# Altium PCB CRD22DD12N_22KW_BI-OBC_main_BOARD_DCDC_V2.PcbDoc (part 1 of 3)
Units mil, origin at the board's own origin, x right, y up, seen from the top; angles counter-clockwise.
Board outline 9308.07 x 7086.6 mil, 4 copper layers (TOP, GND02, POWER03, BOTTOM), stack 74.3 mil thick; 339 components, 177 nets, 874 pads, 199 vias.
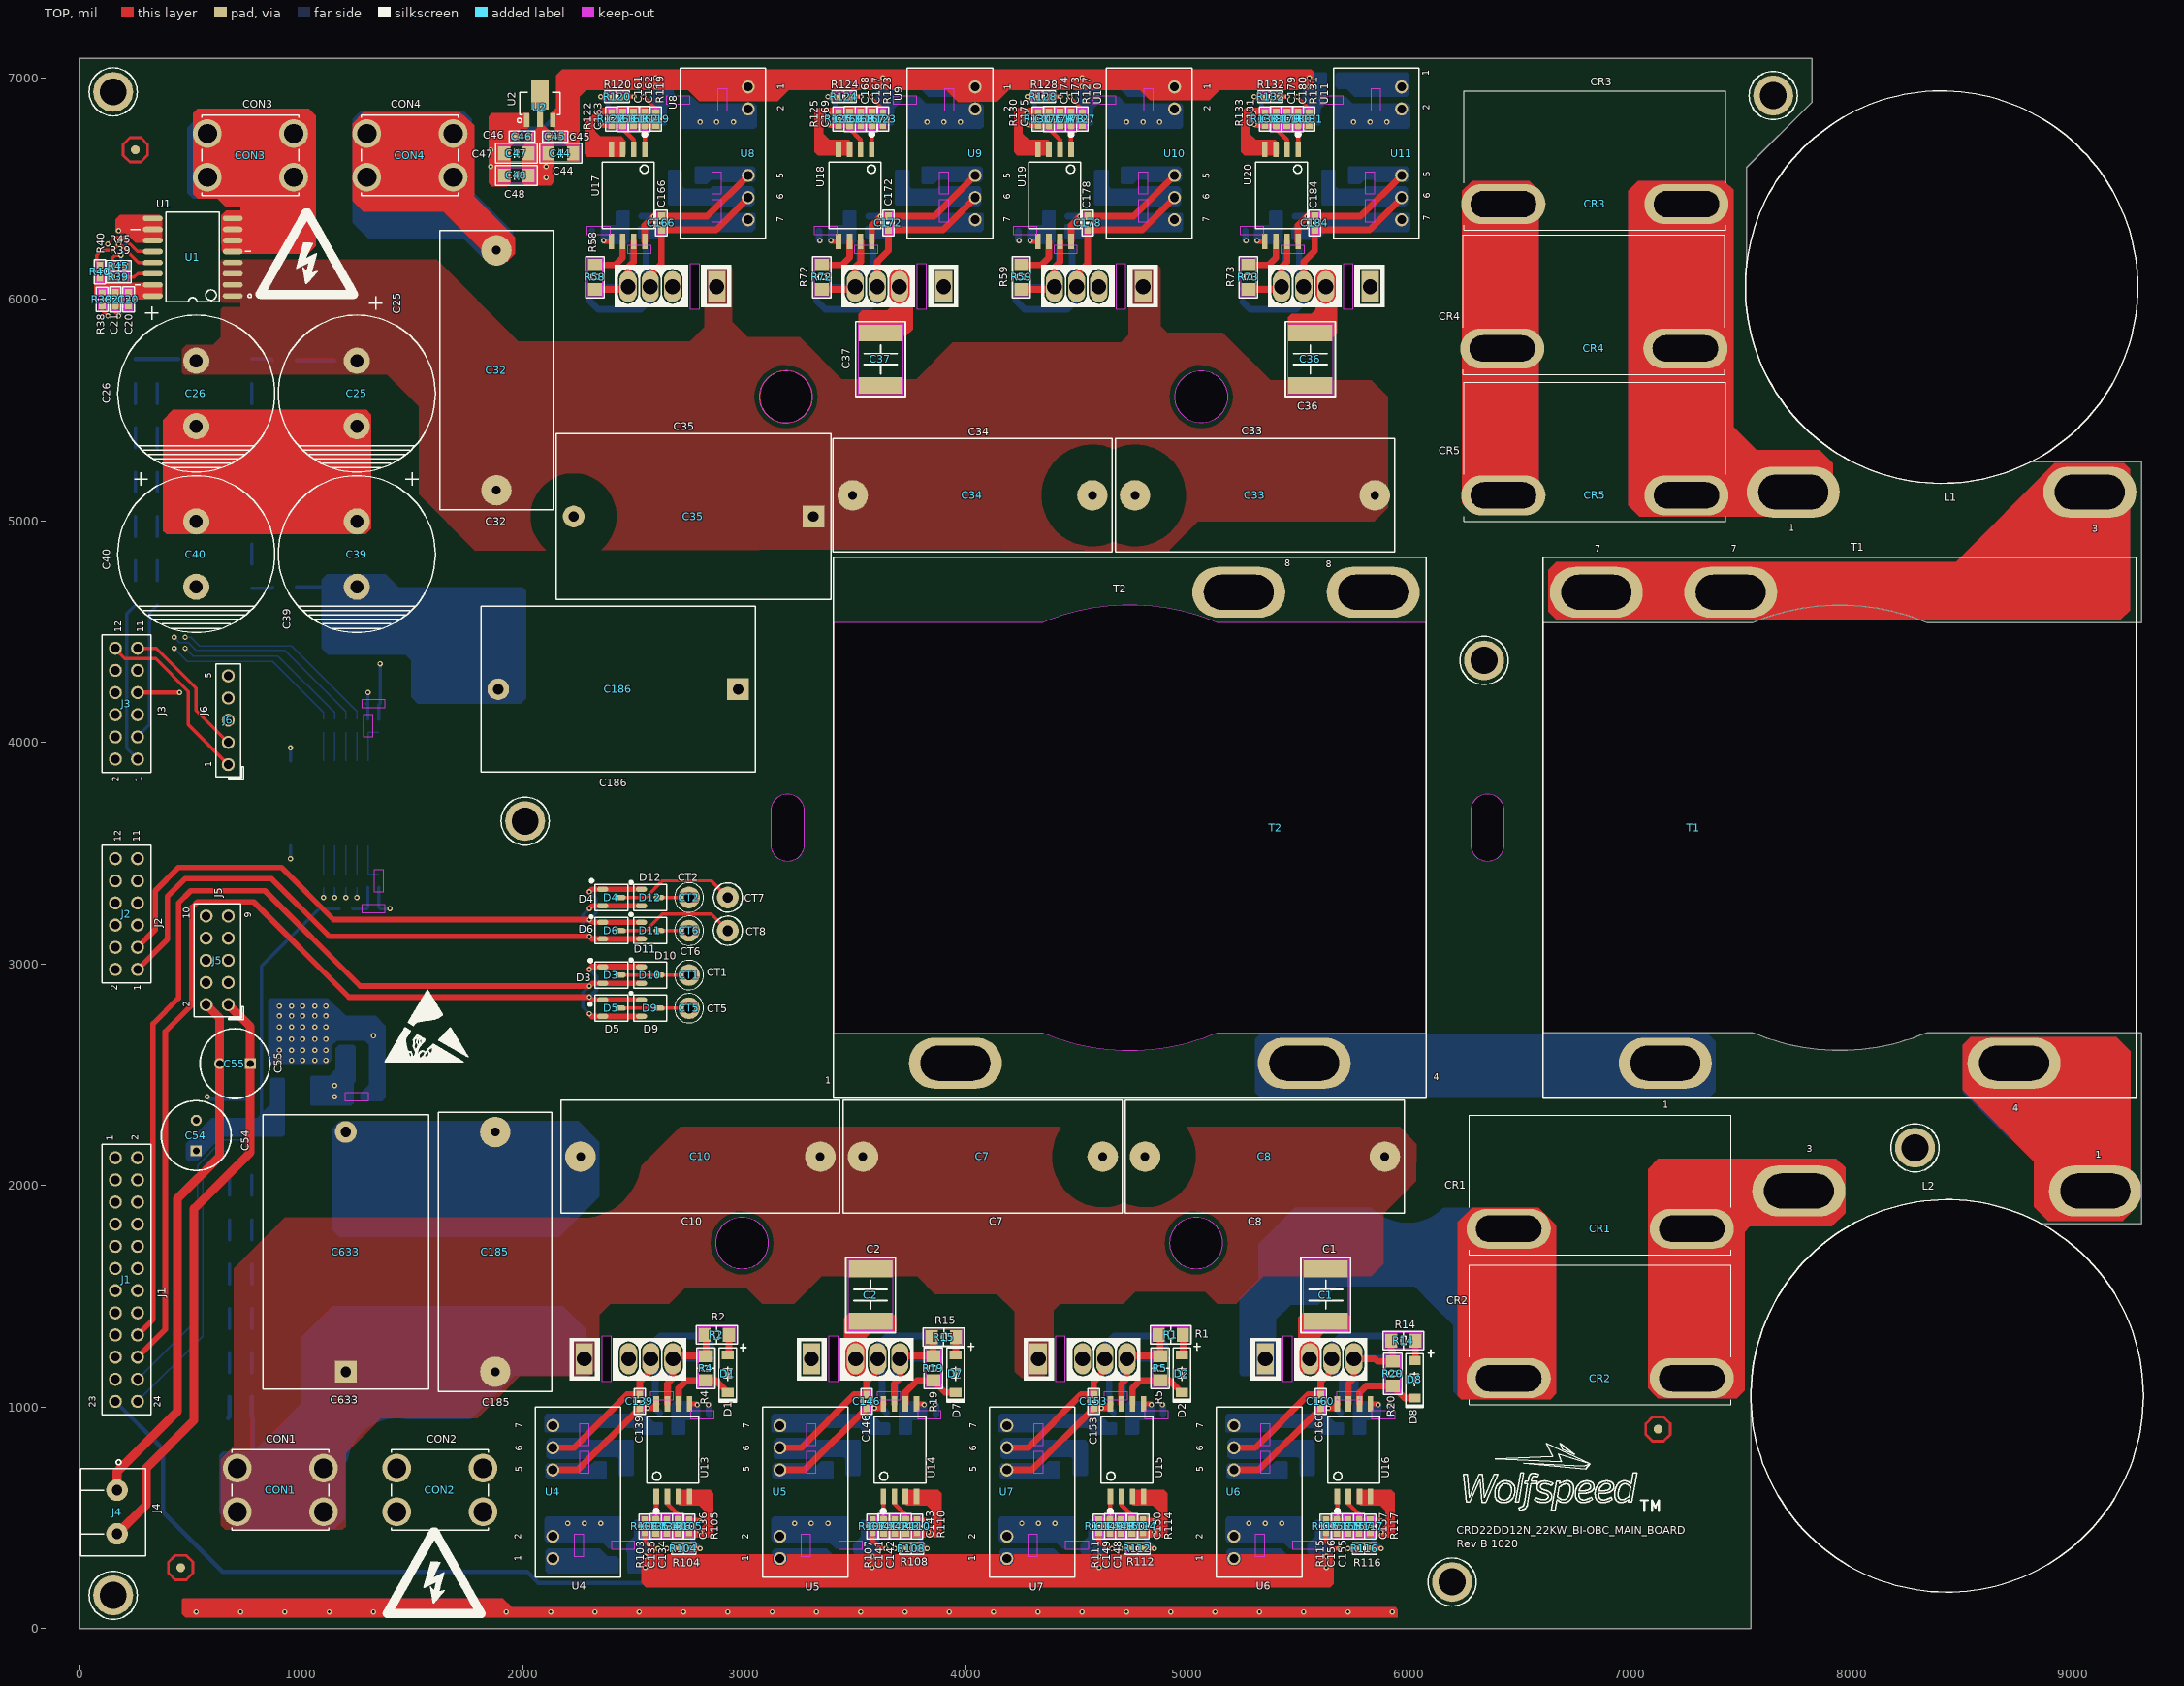
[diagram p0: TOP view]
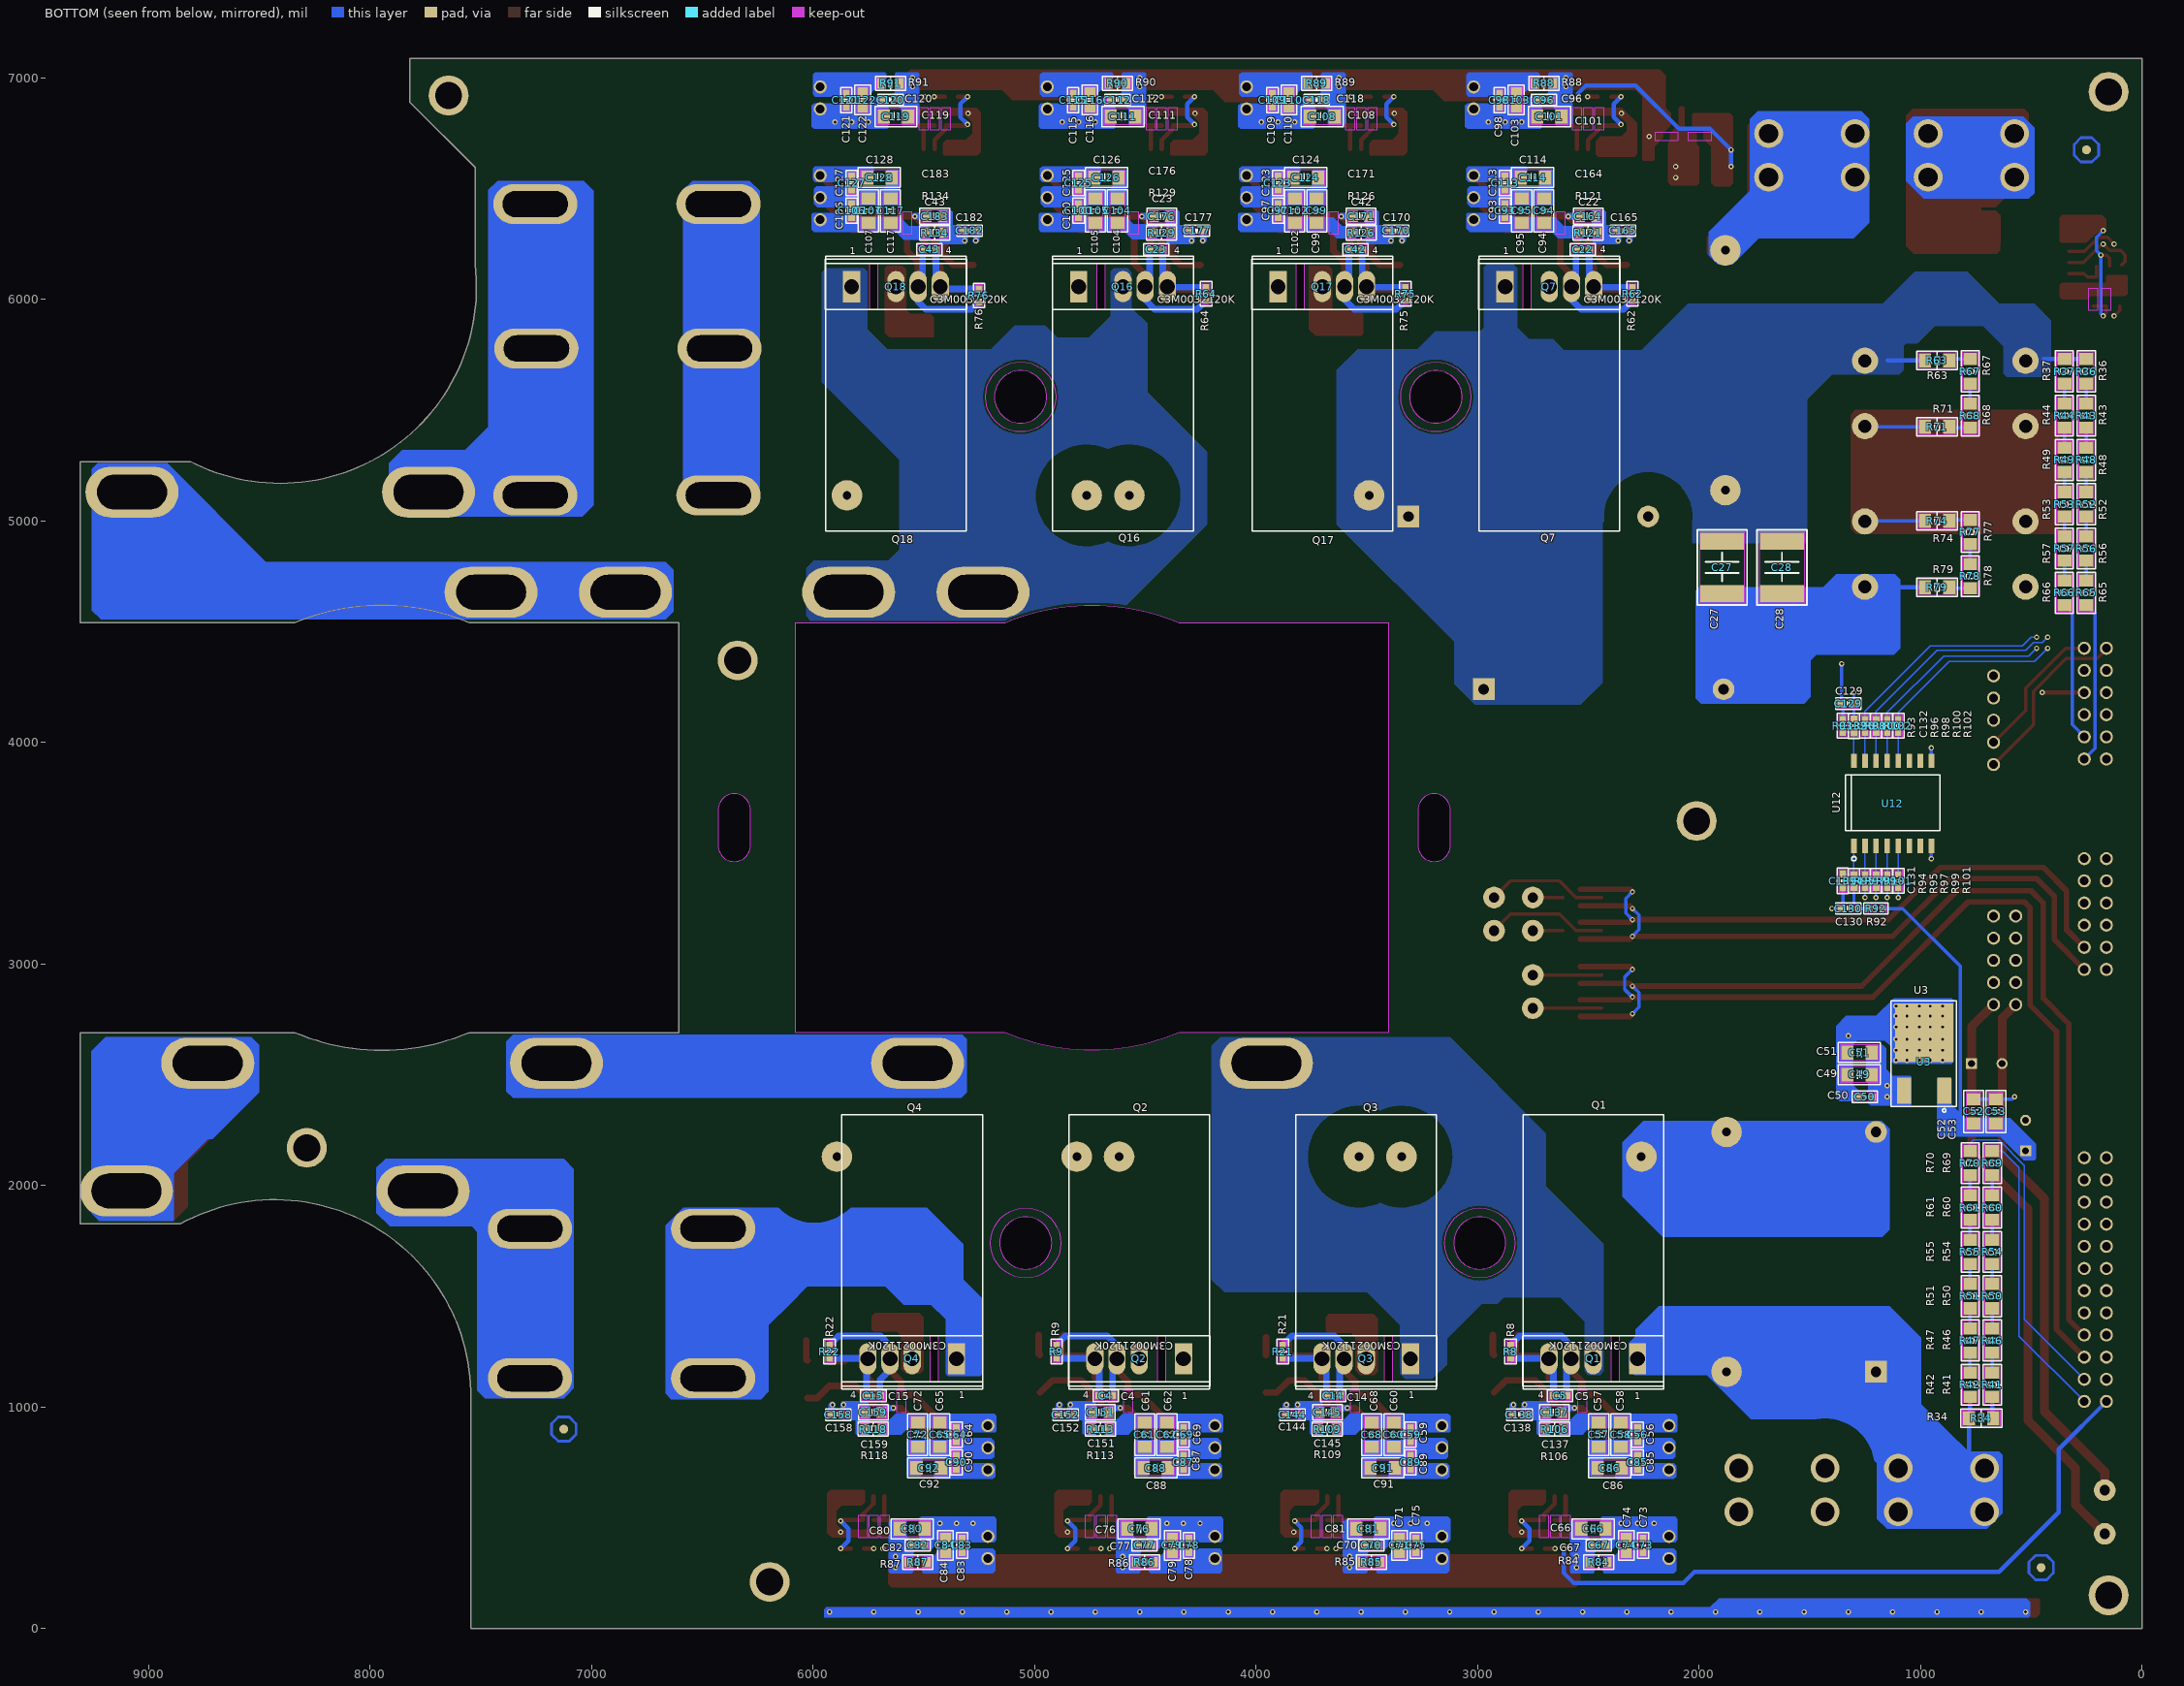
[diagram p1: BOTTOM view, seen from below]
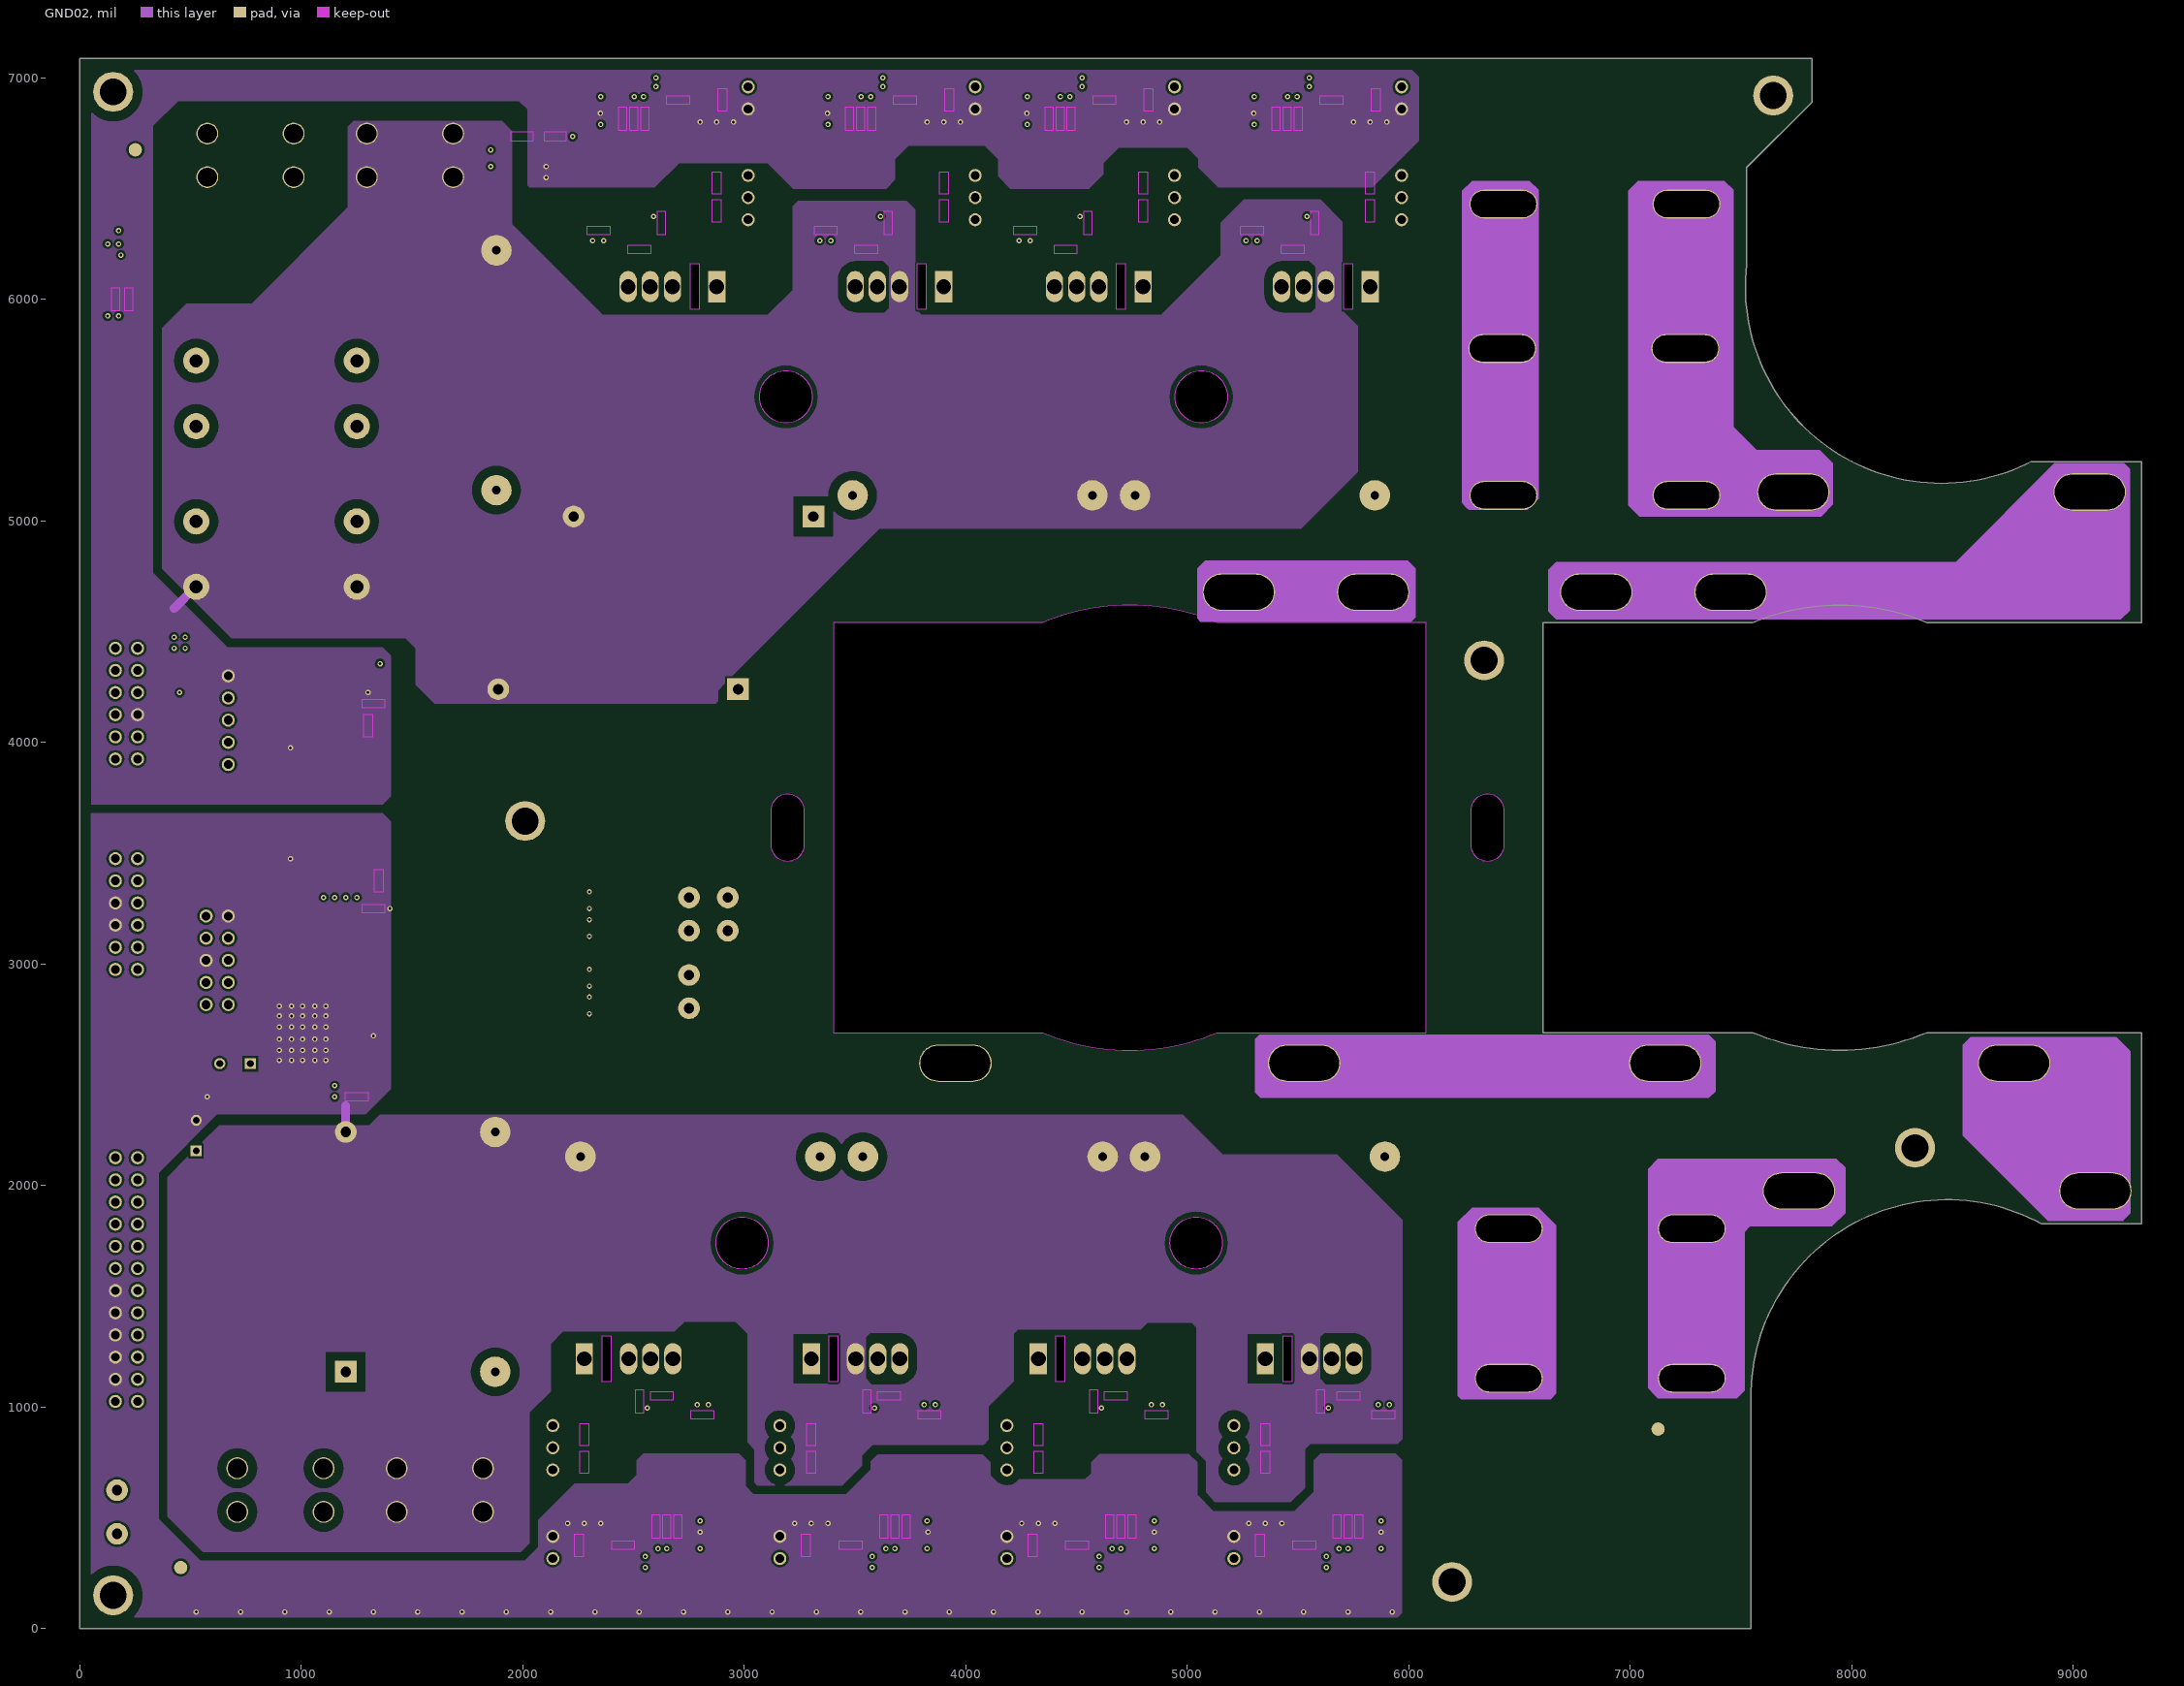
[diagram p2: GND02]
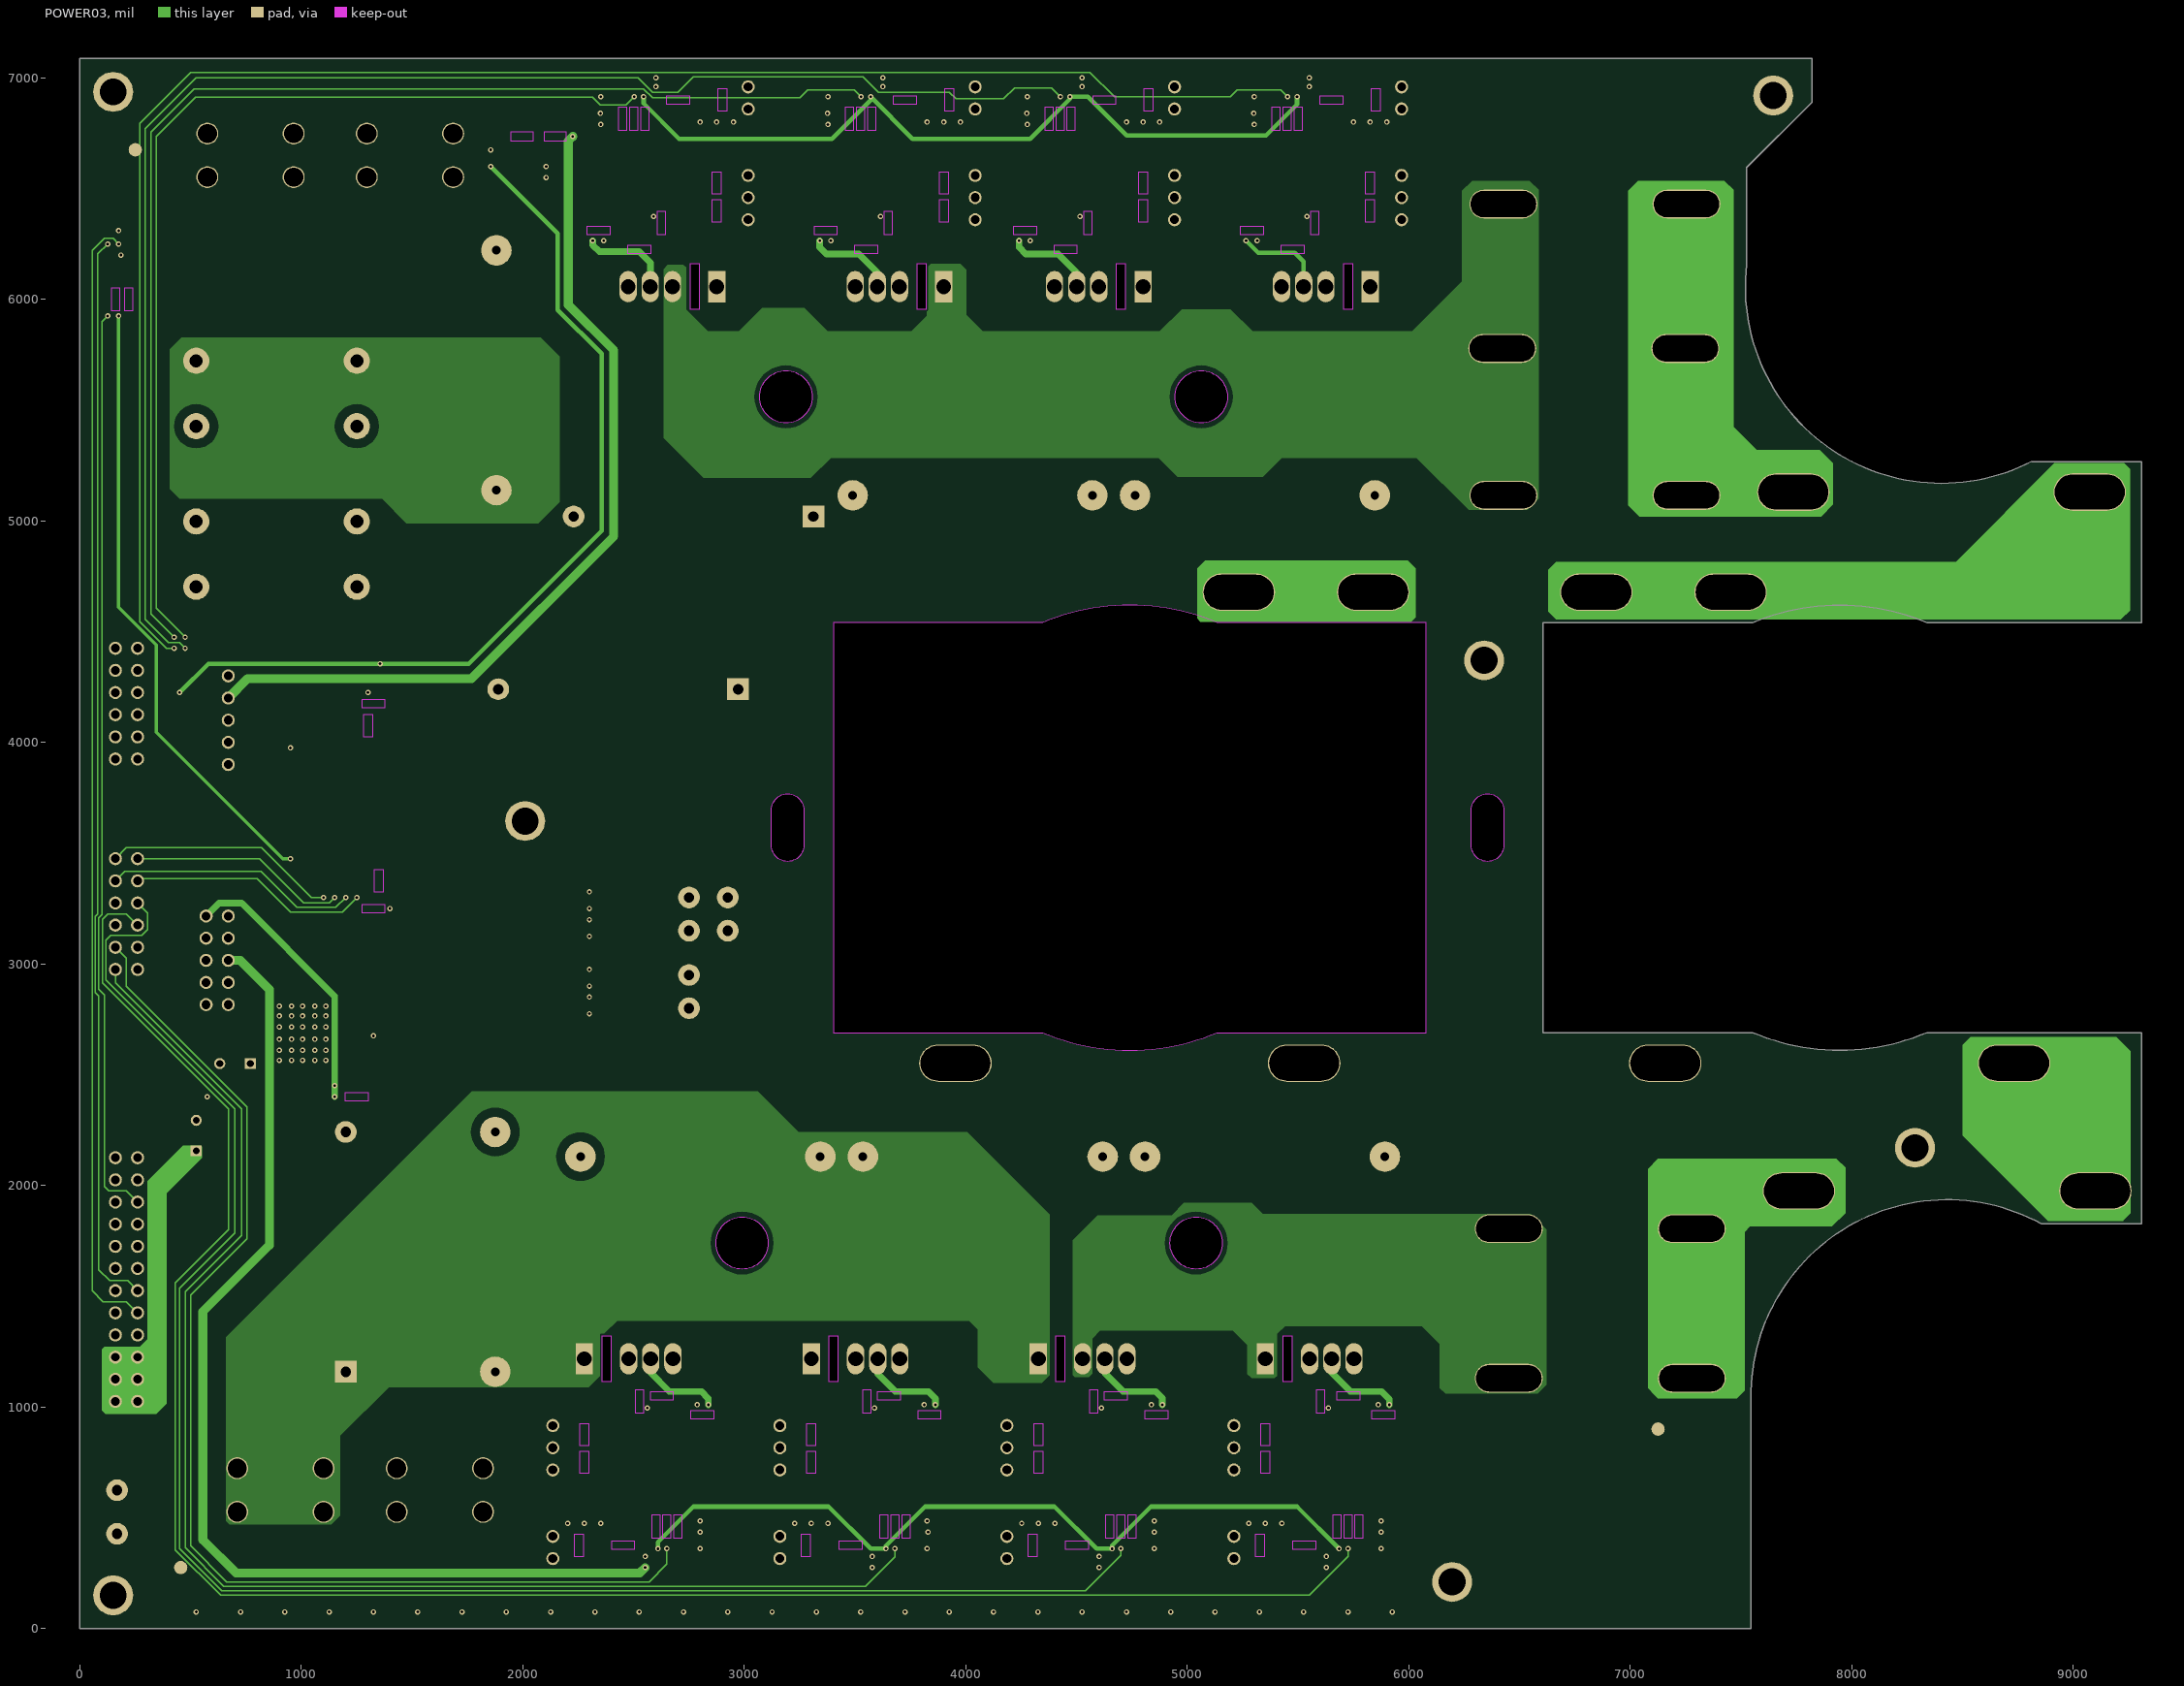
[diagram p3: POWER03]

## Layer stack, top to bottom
Top Solder: solder mask 0.4, Solder Resist, Dk 3.5
TOP: signal copper 2.4
Dielectric 1: core 4.4, FR-4, Dk 4.5
GND02: signal copper 1.2
Dielectric2: core 58.3, FR-4, Dk 1
POWER03: signal copper 1.2
Dielectric3: core 4.4, FR-4, Dk 1
BOTTOM: signal copper 2.4
Bottom Solder: solder mask 0.4, Solder Resist, Dk 3.5

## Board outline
6606,2690 6606,4540 7552.56,4540 cw(c7945.5,3615.03) 9308.07,4540 9308.07,5267.93 8811.07,5267.93 cw(c8405,6055.2) 7525,6595 7820,6890 7820,7086.6 0,7086.6 0,0 7544.23,0 7544.23,229.23 7544.23,1039.59 cw(c8430,1049.8) 9308.07,1826.55 9308.07,2690 8338.44,2690 cw(c7945.5,3615)
cut-out: 6355,3767.5 cw(c6355,3693.5) 6429,3693.5 6429,3536.5 cw(c6355,3536.5) 6355,3462.5 cw(c6355,3536.5) 6281,3536.5 6281,3693.5 cw(c6355,3693.5)
cut-out: 3195,3767.5 cw(c3195,3693.5) 3269,3693.5 3269,3536.5 cw(c3195,3536.5) 3195,3462.5 cw(c3195,3536.5) 3121,3536.5 3121,3693.5 cw(c3195,3693.5)
cut-out: 2989.5,1622 cw(c2989.5,1740) 2871.5,1740 cw(c2989.5,1740) 2989.5,1858 cw(c2989.5,1740) 3107.5,1740 cw(c2989.5,1740)
cut-out: 5039.5,1622 cw(c5039.5,1740) 4921.5,1740 cw(c5039.5,1740) 5039.5,1858 cw(c5039.5,1740) 5157.5,1740 cw(c5039.5,1740)
cut-out: 5062.5,5442 cw(c5062.5,5560) 4944.5,5560 cw(c5062.5,5560) 5062.5,5678 cw(c5062.5,5560) 5180.5,5560 cw(c5062.5,5560)
cut-out: 3187.5,5442 cw(c3187.5,5560) 3069.5,5560 cw(c3187.5,5560) 3187.5,5678 cw(c3187.5,5560) 3305.5,5560 cw(c3187.5,5560)
cut-out: 5133.44,4540 ccw(c4740.5,3615.02) 3402,4540 3402,2690 4347.56,2690 ccw(c4740.5,3615) 6079,2690 6079,4540
cut-out: 5432.31,1322.05 5471.69,1322.05 5471.69,1113.38 5432.31,1113.38
cut-out: 4407.31,1322.05 4446.69,1322.05 4446.69,1113.38 4407.31,1113.38
cut-out: 3382.32,1322.05 3421.68,1322.05 3421.68,1113.38 3382.32,1113.38
cut-out: 2357.32,1322.05 2396.68,1322.05 2396.68,1113.38 2357.32,1113.38
cut-out: 5705.31,6161.61 5744.69,6161.61 5744.69,5952.95 5705.31,5952.95
cut-out: 4680.31,6161.61 4719.69,6161.61 4719.69,5952.95 4680.31,5952.95
cut-out: 3780.32,6161.61 3819.68,6161.61 3819.68,5952.95 3780.32,5952.95
cut-out: 2755.32,6161.61 2794.68,6161.61 2794.68,5952.95 2755.32,5952.95

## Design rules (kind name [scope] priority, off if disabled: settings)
Clearance [All] p1: gap=10 ignorepadtopadclearanceinfootprint=FALSE except(0: Arc-Hole Track-Hole SMDPad-Hole THPad-Hole Via-Hole Fill-Hole Poly-Hole Region-Hole Text-Hole)
PlaneConnect [All] p1: planeconnectstyle=Direct reliefexpansion=20 reliefentries=4 reliefconductorwidth=10 reliefairgap=10
PolygonConnect [All] p1: connectstyle=Direct reliefconductorwidth=10 reliefentries=4 polygonreliefangle="90 Angle" airgapwidth=10
RoutingVias [All] p1: holewidth=28 width=50 viastyle="Through Hole" minholewidth=28 minwidth=50 maxholewidth=28 maxwidth=50
SolderMaskExpansion [All] p1: expansion=4 istentingtop=FALSE
Width [All] p1: maxlimit=10 minlimit=10 preferedwidth=10 impedanceprofiledriven=TRUE minimp=60.000000 maximp=60.000000 favimp=60.000000
29 further rules are at their usual default settings.

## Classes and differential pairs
net class GAO: DCINPUT LEGA LEGB N17988090 N17988199 N17988317 N18067595 SLEGB VO+
net class DI: AGND N16148550 PGND SGND SPGND

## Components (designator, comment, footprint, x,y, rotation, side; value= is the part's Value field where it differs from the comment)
C1 "CAP NP_C2220_0U1" C2220 5625,1505 r270 top
C2 "CAP NP_C2220_0U1" C2220 3570,1505 r270 top
C4 "CAP NP_C0603_1N" C0603#1 4677,1050 r0 bottom
C5 "CAP NP_C0603_1N" C0603#1 2627,1050 r0 bottom
C7 "CAP NP_CAPFILM_31_5X12_5MM_2.2U" CAPFILM_31_5X12_5MM 4076.17,2130 r0 top
C8 "CAP NP_CAPFILM_31_5X12_5MM_2.2U" CAPFILM_31_5X12_5MM 5350,2130 r180 top
C10 "CAP NP_CAPFILM_31_5X12_5MM_2.2U" CAPFILM_31_5X12_5MM 2801.17,2130 r180 top
C14 "CAP NP_C0603_1N" C0603#1 3652,1050 r0 bottom
C15 "CAP NP_C0603_1N" C0603#1 5727,1050 r0 bottom
C20 "CAP NP_C0603_0.1U" C0603#2 220,6000 r270 top
C21 "CAP NP_C0603_1U" C0603#2 160,6000 r270 top
C22 "CAP NP_C0603_1N" C0603#2 2525,6225 r0 bottom
C23 "CAP NP_C0603_1N" C0603#2 4450,6225 r0 bottom
C25 "CAP POL_ECAP_D18P7_5_450V 180UF" ECAP_D18P7_5 1250,5575 r180 top
C26 "CAP POL_ECAP_D18P7_5_450V 180UF" ECAP_D18P7_5 525,5575 r180 top
C27 "CAP NP_C2220_0U1" C2220 1895,4790 r270 bottom
C28 "CAP NP_C2220_0U1" C2220 1625,4790 r270 bottom
C32 "CAP NP_CAPFILM_31_5X12_5MM_2.2U" CAPFILM_31_5X12_5MM 1880,5680 r90 top
C33 "CAP NP_CAPFILM_31_5X12_5MM_2.2U" CAPFILM_31_5X12_5MM 5305,5115 r180 top
C34 "CAP NP_CAPFILM_31_5X12_5MM_2.2U" CAPFILM_31_5X12_5MM 4030,5115 r0 top
C35 "CAP NP_CAPFILM_31_5X18_5MM_5U" CAPFILM_31_5X18_5MM 2770,5020 r180 top
C36 "CAP NP_C2220_0U1" C2220 5555,5730 r90 top
C37 "CAP NP_C2220_0U1" C2220 3615,5730 r90 top
C39 "CAP POL_ECAP_D18P7_5_450V 180UF" ECAP_D18P7_5 1250,4850 r180 top
C40 "CAP POL_ECAP_D18P7_5_450V 180UF" ECAP_D18P7_5 525,4850 r180 top
C42 "CAP NP_C0603_1N" C0603#2 3550,6225 r0 bottom
C43 "CAP NP_C0603_1N" C0603#2 5475,6225 r0 bottom
C44 "CAP NP_C1206_10U" C1206#1 2170.75,6659.25 r0 top
C45 "CAP NP_C0603_1U" C0603#2 2145.75,6734.25 r0 top
C46 "CAP NP_C0603_1U" C0603#2 1995.75,6734.25 r180 top
C47 "CAP NP_C1206_22U" C1206#1 1970.75,6659.25 r180 top
C48 "CAP NP_C1206_22U" C1206#1 1970.75,6559.25 r180 top
C49 "CAP NP_C1206_10U" C1206#2 1275,2500 r0 bottom
C50 "CAP NP_C0603_1U" C0603#1 1250,2400 r0 bottom
C51 "CAP NP_C1206_10U" C1206#2 1275,2600 r0 bottom
C52 "CAP NP_C1206_10U" C1206#1 759.25,2334.25 r270 bottom
C53 "CAP NP_C1206_10U" C1206#1 659.25,2334.25 r270 bottom
C54 "CAP POL_ECAP_D8P3_5_25V 220UF" ECAP_D8P3_5 525,2225 r90 top
C55 "CAP POL_ECAP_D8P3_5_25V 220UF" ECAP_D8P3_5 700,2550 r180 top
C56 "CAP NP_C0603_1UF" C0603#2 2277,875 r270 bottom
C57 "CAP NP_C1206_4U7" C1206#1 2452,875 r270 bottom
C58 "CAP NP_C1206_10UF" C1206#1 2352,875 r270 bottom
C59 "CAP NP_C0603_1UF" C0603#2 3302,875 r270 bottom
C60 "CAP NP_C1206_10UF" C1206#1 3377,875 r270 bottom
C61 "CAP NP_C1206_4U7" C1206#1 4502,875 r270 bottom
C62 "CAP NP_C1206_10UF" C1206#1 4402,875 r270 bottom
C64 "CAP NP_C0603_1UF" C0603#2 5352,875 r270 bottom
C65 "CAP NP_C1206_10UF" C1206#1 5427,875 r270 bottom
C66 "CAP NP_C1206_10UF" C1206#2 2477,450 r0 bottom
C67 "CAP NP_C0603_1UF" C0603#1 2452,375 r0 bottom
C68 "CAP NP_C1206_4U7" C1206#1 3477,875 r270 bottom
C69 "CAP NP_C0603_1UF" C0603#2 4327,875 r270 bottom
C70 "CAP NP_C0603_1UF" C0603#1 3479.17,375 r0 bottom
C71 "CAP NP_C0805_2U2" C0805#1 3352,375 r90 bottom
C72 "CAP NP_C1206_4U7" C1206#1 5527,875 r270 bottom
C73 "CAP NP_C0603_0U1" C0603#2 2252,375 r90 bottom
C74 "CAP NP_C0805_2U2" C0805#1 2327,375 r90 bottom
C75 "CAP NP_C0603_0U1" C0603#2 3277,375 r90 bottom
C76 "CAP NP_C1206_10UF" C1206#2 4527,450 r0 bottom
C77 "CAP NP_C0603_1UF" C0603#1 4502,375 r0 bottom
C78 "CAP NP_C0603_0U1" C0603#2 4302,375 r90 bottom
C79 "CAP NP_C0805_2U2" C0805#1 4377,375 r90 bottom
C80 "CAP NP_C1206_10UF" C1206#2 5552,450 r0 bottom
C81 "CAP NP_C1206_10UF" C1206#2 3491.67,450 r0 bottom
C82 "CAP NP_C0603_1UF" C0603#1 5527,375 r0 bottom
C83 "CAP NP_C0603_0U1" C0603#2 5327,375 r90 bottom
C84 "CAP NP_C0805_2U2" C0805#1 5402,375 r90 bottom
C85 "CAP NP_C0603_1UF" C0603#2 2277,750 r270 bottom
C86 "CAP NP_C1206_10UF" C1206#2 2402,725 r0 bottom
C87 "CAP NP_C0603_1UF" C0603#2 4327,750 r270 bottom
C88 "CAP NP_C1206_10UF" C1206#2 4452,725 r0 bottom
C89 "CAP NP_C0603_1UF" C0603#2 3302,750 r270 bottom
C90 "CAP NP_C0603_1UF" C0603#2 5352,750 r270 bottom
C91 "CAP NP_C1206_10UF" C1206#2 3427,725 r0 bottom
C92 "CAP NP_C1206_10UF" C1206#2 5477,725 r0 bottom
C93 "CAP NP_C0603_1UF" C0603#2 2875,6400 r90 bottom
C94 "CAP NP_C1206_4U7" C1206#1 2700,6400 r90 bottom
C95 "CAP NP_C1206_10UF" C1206#1 2800,6400 r90 bottom
C96 "CAP NP_C0603_1UF" C0603#2 2700,6900 r0 bottom
C97 "CAP NP_C0603_1UF" C0603#2 3900,6400 r90 bottom
C98 "CAP NP_C0603_0U1" C0603#2 2900,6900 r270 bottom
C99 "CAP NP_C1206_4U7" C1206#1 3725,6400 r90 bottom
C100 "CAP NP_C0603_1UF" C0603#2 4800,6400 r90 bottom
C101 "CAP NP_C1206_10UF" C1206#1 2675,6825 r0 bottom
C102 "CAP NP_C1206_10UF" C1206#1 3825,6400 r90 bottom
C103 "CAP NP_C0805_2U2" C0805#1 2825,6900 r270 bottom
C104 "CAP NP_C1206_4U7" C1206#1 4625,6400 r90 bottom
C105 "CAP NP_C1206_10UF" C1206#1 4725,6400 r90 bottom
C106 "CAP NP_C0603_1UF" C0603#2 5825,6400 r90 bottom
C107 "CAP NP_C1206_10UF" C1206#1 5750,6400 r90 bottom
C108 "CAP NP_C1206_10UF" C1206#1 3700,6825 r0 bottom
C109 "CAP NP_C0603_0U1" C0603#2 3925,6900 r270 bottom
C110 "CAP NP_C0805_2U2" C0805#1 3850,6900 r270 bottom
C111 "CAP NP_C1206_10UF" C1206#1 4600,6825 r0 bottom
C112 "CAP NP_C0603_1UF" C0603#2 4625,6900 r0 bottom
C113 "CAP NP_C0603_1UF" C0603#2 2875,6525 r90 bottom
C114 "CAP NP_C1206_10UF" C1206#1 2750,6550 r0 bottom
C115 "CAP NP_C0603_0U1" C0603#2 4825,6900 r270 bottom
C116 "CAP NP_C0805_2U2" C0805#1 4750,6900 r270 bottom
C117 "CAP NP_C1206_4U7" C1206#1 5650,6400 r90 bottom
C118 "CAP NP_C0603_1UF" C0603#2 3725,6900 r0 bottom
C119 "CAP NP_C1206_10UF" C1206#1 5625,6825 r0 bottom
C120 "CAP NP_C0603_1UF" C0603#2 5650,6900 r0 bottom
C121 "CAP NP_C0603_0U1" C0603#2 5850,6900 r270 bottom
C122 "CAP NP_C0805_2U2" C0805#1 5775,6900 r270 bottom
C123 "CAP NP_C0603_1UF" C0603#2 3900,6525 r90 bottom
C124 "CAP NP_C1206_10UF" C1206#1 3775,6550 r0 bottom
C125 "CAP NP_C0603_1UF" C0603#2 4800,6525 r90 bottom
C126 "CAP NP_C1206_10UF" C1206#1 4675,6550 r0 bottom
C127 "CAP NP_C0603_1UF" C0603#2 5825,6525 r90 bottom
C128 "CAP NP_C1206_10UF" C1206#1 5700,6550 r0 bottom
C129 "CAP NP_C0603_0U1" C0603#1 1325,4175 r0 bottom
C130 "CAP NP_C0603_0U1" C0603#2 1325,3250 r0 bottom
C131 "CAP NP_C0603_0U1" C0603#2 1350,3375 r90 bottom
C132 "CAP NP_C0603_0U1" C0603#2 1300,4075 r270 bottom
C134 "CAP NP_C0603_1U" C0603#2 2650,460.68 r270 top
C135 "CAP NP_C0603_0.1U" C0603#2 2600,460.68 r270 top
C136 "CAP NP_C0603_1N" C0603#2 2700,460.68 r270 top
C137 "CAP NP_C0805_2.2U" C0805#2 2652,975 r0 bottom
C138 "CAP NP_C0603_1U" C0603#2 2810,965 r0 bottom
C139 "CAP NP_C0603_1U" C0603#2 2527,1025 r270 top
C141 "CAP NP_C0603_1U" C0603#2 3629.17,460.68 r270 top
C142 "CAP NP_C0603_0.1U" C0603#2 3679.17,460.68 r270 top
C143 "CAP NP_C0603_1N" C0603#2 3729.17,460.68 r270 top
C144 "CAP NP_C0603_1U" C0603#2 3835,965 r0 bottom
C145 "CAP NP_C0805_2.2U" C0805#2 3677,975 r0 bottom
C146 "CAP NP_C0603_1U" C0603#2 3552,1025 r270 top
C148 "CAP NP_C0603_1U" C0603#2 4700,460.68 r270 top
C149 "CAP NP_C0603_0.1U" C0603#2 4650,460.68 r270 top
C150 "CAP NP_C0603_1N" C0603#2 4750,460.68 r270 top
C151 "CAP NP_C0805_2.2U" C0805#2 4702,975 r0 bottom
C152 "CAP NP_C0603_1U" C0603#2 4860,965 r0 bottom
C153 "CAP NP_C0603_1U" C0603#2 4577,1025 r270 top
C155 "CAP NP_C0603_1U" C0603#2 5725,460.68 r270 top
C156 "CAP NP_C0603_0.1U" C0603#2 5675,460.68 r270 top
C157 "CAP NP_C0603_1N" C0603#2 5775,460.68 r270 top
C158 "CAP NP_C0603_1U" C0603#2 5885,965 r0 bottom
C159 "CAP NP_C0805_2.2U" C0805#2 5727,975 r0 bottom
C160 "CAP NP_C0603_1U" C0603#2 5602,1025 r270 top
C161 "CAP NP_C0603_1U" C0603#2 2500,6814.32 r90 top
C162 "CAP NP_C0603_0.1U" C0603#2 2550,6814.32 r90 top
C163 "CAP NP_C0603_1N" C0603#2 2450,6814.32 r90 top
C164 "CAP NP_C0805_2.2U" C0805#1 2500,6375 r0 bottom
C165 "CAP NP_C0603_1U" C0603#1 2342,6310 r0 bottom
C166 "CAP NP_C0603_1U" C0603#2 2625,6344.66 r90 top
C167 "CAP NP_C0603_1U" C0603#2 3575,6814.32 r90 top
C168 "CAP NP_C0603_0.1U" C0603#2 3525,6814.32 r90 top
C169 "CAP NP_C0603_1N" C0603#2 3475,6814.32 r90 top
C170 "CAP NP_C0603_1U" C0603#1 3367,6310 r0 bottom
C171 "CAP NP_C0805_2.2U" C0805#1 3525,6375 r0 bottom
C172 "CAP NP_C0603_1U" C0603#2 3650,6344.66 r90 top
C173 "CAP NP_C0603_0.1U" C0603#2 4475,6814.32 r90 top
C174 "CAP NP_C0603_1U" C0603#2 4425,6814.32 r90 top
C175 "CAP NP_C0603_1N" C0603#2 4375,6814.32 r90 top
C176 "CAP NP_C0805_2.2U" C0805#1 4425,6375 r0 bottom
C177 "CAP NP_C0603_1U" C0603#1 4267,6310 r0 bottom
C178 "CAP NP_C0603_1U" C0603#2 4550,6344.66 r90 top
C179 "CAP NP_C0603_1U" C0603#2 5450,6814.32 r90 top
C180 "CAP NP_C0603_0.1U" C0603#2 5500,6814.32 r90 top
C181 "CAP NP_C0603_1N" C0603#2 5400,6814.32 r90 top
C182 "CAP NP_C0603_1U" C0603#1 5292,6310 r0 bottom
C183 "CAP NP_C0805_2.2U" C0805#1 5450,6375 r0 bottom
C184 "CAP NP_C0603_1U" C0603#2 5575,6344.66 r90 top
C185 "CAP NP_CAPFILM_31_5X12_5MM_2.2U" CAPFILM_31_5X12_5MM 1875,1700 r90 top
C186 "CAP NP_CAPFILM_31_5X18_5MM_5U" CAPFILM_31_5X18_5MM 2430,4240 r180 top
C633 "CAP NP_CAPFILM_31_5X18_5MM_5U" CAPFILM_31_5X18_5MM 1200,1700 r90 top
CON1 "CONNECTER_THREAD4_9P9X5_1110X92" THREAD4_9P9X5_1110X920 905,625 r180 top
CON2 "CONNECTER_THREAD4_9P9X5_1110X92" THREAD4_9P9X5_1110X920 1625,625 r180 top
CON3 "CONNECTER_THREAD4_9P9X5_1110X92" THREAD4_9P9X5_1110X920 770,6650 r180 top
CON4 "CONNECTER_THREAD4_9P9X5_1110X92" THREAD4_9P9X5_1110X920 1490,6650 r180 top
CR1 "3PIN_CRB_3PIN" CRB 6864.06,2001.38 r180 top
CR2 "3PIN_CRB_3PIN" CRB 6864.06,1326.38 r180 top
CR3 "3PIN_CRB_3PIN" CRB 6840,6626.85 r180 top
CR4 "3PIN_CRB_3PIN" CRB 6835,5975 r180 top
CR5 "3PIN_CRB_3PIN" CRB 6840,5311.85 r180 top
CT1 "CON1_2_TH47_CR98_T1T2" TH47_CR98 2750,2950 r270 top
CT2 "CON1_2_TH47_CR98_T1T2" TH47_CR98 2750,3300 r270 top
CT5 "CON1_2_TH47_CR98_T1T2" TH47_CR98 2750,2800 r270 top
CT6 "CON1_2_TH47_CR98_T1T2" TH47_CR98 2750,3150 r270 top
CT7 "CON1_2_TH47_CR98_T1T2" TH47_CR98 2925,3300 r0 top
CT8 "CON1_2_TH47_CR98_T1T2" TH47_CR98 2925,3150 r0 top
D1 "DIODE_0_SOD-123_SL14PL-TP" SOD-123 2925,1150 r270 top
D2 "DIODE_0_SOD-123_SL14PL-TP" SOD-123 4975,1150 r270 top
D3 "FMMD6100/SOT_0_SOT-23_BAT754S" SOT-23 2400,2950 r270 top
D4 "FMMD6100/SOT_0_SOT-23_BAT754S" SOT-23 2400,3300 r270 top
D5 "FMMD6100/SOT_0_SOT-23_BAT754S" SOT-23 2400,2800 r270 top
D6 "FMMD6100/SOT_0_SOT-23_BAT754S" SOT-23 2400,3150 r270 top
D7 "DIODE_0_SOD-123_SL14PL-TP" SOD-123 3954.17,1150 r270 top
D8 "DIODE_0_SOD-123_SL14PL-TP" SOD-123 6025,1125 r270 top
D9 "FMMD6100/SOT_0_SOT-23_BAT754S" SOT-23 2575,2800 r270 top
D10 "FMMD6100/SOT_0_SOT-23_BAT754S" SOT-23 2575,2950 r270 top
D11 "FMMD6100/SOT_0_SOT-23_BAT754S" SOT-23 2575,3150 r270 top
D12 "FMMD6100/SOT_0_SOT-23_BAT754S" SOT-23 2575,3300 r270 top
J1 "CON24A_CON_2MM54_12X2_CON24A" CON_2MM54_12X2 210,1575 r270 top
J2 "CON12A_CON_2MM54_6X2_CON12A" CON_2MM54_6X2 210,3225 r90 top
J3 "CON12A_CON_2MM54_6X2_CON12A" CON_2MM54_6X2 210,4175 r90 top
J4 "CON2_CON_5MM_2X1_CON2" CON_5MM_2X1 150,525 r270 top
J5 "CON10A_CON_2MM54_5X2_CON10A" CON_2MM54_5X2 626.41,3009.25 r90 top
J6 "CON5_CON_2MM54_5X1_CON5" CON_2MM54_5X1 676.41,4093.35 r90 top
L1 "126LNS_1_L6_8U" L6 8405,5969.37 r0 top
L2 "126LNS_5_L6_8U" L6 8430,1135.63 r180 top
Q1 "C3M0065090J_4_TO-247-4L_C3M0021" TO-247-4L#1 2477,1700 r0 bottom
Q2 "C3M0065090J_4_TO-247-4L_C3M0021" TO-247-4L#1 4527,1700 r0 bottom
Q3 "C3M0065090J_4_TO-247-4L_C3M0021" TO-247-4L#1 3502,1700 r0 bottom
Q4 "C3M0065090J_4_TO-247-4L_C3M0021" TO-247-4L#1 5552,1700 r0 bottom
Q7 "C3M0065090J_4_TO-247-4L_C3M0032" TO-247-4L#2 2675,5575 r0 bottom
Q16 "C3M0065090J_4_TO-247-4L_C3M0032" TO-247-4L#2 4600,5575 r0 bottom
Q17 "C3M0065090J_4_TO-247-4L_C3M0032" TO-247-4L#2 3700,5575 r0 bottom
Q18 "C3M0065090J_4_TO-247-4L_C3M0032" TO-247-4L#2 5625,5575 r0 bottom
R1 "R_R1206_4.3R" R1206#1 4925,1325 r180 top
R2 "R_R1206_4.3R" R1206#1 2875,1325 r0 top
R4 "R_R1206_10R" R1206#1 2827,1175 r270 top
R5 "R_R1206_10R" R1206#1 4877,1175 r90 top
R8 "R_R0603_10K" R0603 2850,1250 r270 bottom
R9 "R_R0603_10K" R0603 4900,1250 r270 bottom
R14 "R_R1206_4.3R" R1206#1 5975,1300 r180 top
R15 "R_R1206_4.3R" R1206#1 3900,1315 r0 top
R19 "R_R1206_10R" R1206#1 3852,1175 r270 top
R20 "R_R1206_10R" R1206#1 5927,1150 r90 top
R21 "R_R0603_10K" R0603 3879.17,1250 r270 bottom
R22 "R_R0603_10K" R0603 5925,1250 r270 bottom
R34 "RESISTOR_R1206_0R" R1206#1 725,950 r0 bottom
R36 "R_R1206_620K" R1206#1 250,5675 r270 bottom
R37 "R_R1206_620K" R1206#1 350,5675 r270 bottom
R38 "R_R0603_10R" R0603 100,6000 r90 top
R39 "R_R0603_6.8K" R0603 175,6100 r0 top
R40 "R_R0603_10K" R0603 90,6125 r90 top
R41 "RESISTOR_R1206_620K" R1206#1 675,1100 r270 bottom
R42 "RESISTOR_R1206_620K" R1206#1 775,1100 r270 bottom
R43 "R_R1206_620K" R1206#1 250,5475 r270 bottom
R44 "R_R1206_620K" R1206#1 350,5475 r270 bottom
R45 "R_R0603_1.8K" R0603 175,6150 r180 top
R46 "RESISTOR_R1206_620K" R1206#1 675,1300 r270 bottom
R47 "RESISTOR_R1206_620K" R1206#1 775,1300 r270 bottom
R48 "R_R1206_620K" R1206#1 250,5275 r270 bottom
R49 "R_R1206_620K" R1206#1 350,5275 r270 bottom
R50 "RESISTOR_R1206_620K" R1206#1 675,1500 r270 bottom
R51 "RESISTOR_R1206_620K" R1206#1 775,1500 r270 bottom
R52 "R_R1206_620K" R1206#1 250,5075 r270 bottom
R53 "R_R1206_620K" R1206#1 350,5075 r270 bottom
R54 "RESISTOR_R1206_620K" R1206#1 675,1700 r270 bottom
R55 "RESISTOR_R1206_620K" R1206#1 775,1700 r270 bottom
R56 "R_R1206_620K" R1206#1 250,4875 r270 bottom
R57 "R_R1206_620K" R1206#1 350,4875 r270 bottom
R58 "R_R1206_10R" R1206#1 2325,6100 r90 top
R59 "R_R1206_10R" R1206#1 4250,6100 r270 top
R60 "RESISTOR_R1206_620K" R1206#1 675,1900 r270 bottom
R61 "RESISTOR_R1206_620K" R1206#1 775,1900 r270 bottom
R62 "R_R0603_10K" R0603 2300,6025 r90 bottom
R63 "RESISTOR_R1206_510K" R1206#2 925,5725 r0 bottom
R64 "R_R0603_10K" R0603 4225,6025 r90 bottom
R65 "R_R1206_620K" R1206#1 250,4675 r270 bottom
R66 "R_R1206_620K" R1206#1 350,4675 r270 bottom
R67 "RESISTOR_R1206_510K" R1206#1 775,5675 r270 bottom
R68 "RESISTOR_R1206_510K" R1206#1 775,5475 r270 bottom
R69 "RESISTOR_R1206_620K" R1206#1 675,2100 r270 bottom
R70 "RESISTOR_R1206_620K" R1206#1 775,2100 r270 bottom
R71 "RESISTOR_R1206_510K" R1206#1 925,5425 r0 bottom
R72 "R_R1206_9R1" R1206#1 3350,6100 r90 top
R73 "R_R1206_9R1" R1206#1 5275,6100 r270 top
R74 "RESISTOR_R1206_510K" R1206#2 925,5000 r0 bottom
R75 "R_R0603_10K" R0603 3325,6025 r90 bottom
R76 "R_R0603_10K" R0603 5250,6017.72 r90 bottom
R77 "RESISTOR_R1206_510K" R1206#1 775,4950 r270 bottom
R78 "RESISTOR_R1206_510K" R1206#1 775,4750 r270 bottom
R79 "RESISTOR_R1206_510K" R1206#1 925,4700 r0 bottom
R84 "RESISTOR_R0805_1R" R0805#1 2452,300 r0 bottom
R85 "RESISTOR_R0805_1R" R0805#1 3479.17,300 r0 bottom
R86 "RESISTOR_R0805_1R" R0805#1 4502,300 r0 bottom
R87 "RESISTOR_R0805_1R" R0805#1 5527,300 r0 bottom
R88 "RESISTOR_R0805_1R" R0805#2 2700,6975 r0 bottom
R89 "RESISTOR_R0805_1R" R0805#2 3725,6975 r0 bottom
R90 "RESISTOR_R0805_1R" R0805#2 4625,6975 r0 bottom
R91 "RESISTOR_R0805_1R" R0805#2 5650,6975 r0 bottom
R92 "RESISTOR_R0603_10R" R0603 1200,3250 r0 bottom
R93 "RESISTOR_R0603_10R" R0603 1350,4075 r90 bottom
R94 "RESISTOR_R0603_10R" R0603 1300,3375 r270 bottom
R95 "RESISTOR_R0603_51R" R0603 1250,3375 r270 bottom
R96 "RESISTOR_R0603_51R" R0603 1250,4075 r90 bottom
R97 "RESISTOR_R0603_51R" R0603 1200,3375 r270 bottom
R98 "RESISTOR_R0603_51R" R0603 1200,4075 r90 bottom
R99 "RESISTOR_R0603_51R" R0603 1150,3375 r270 bottom
R100 "RESISTOR_R0603_51R" R0603 1150,4075 r90 bottom
R101 "RESISTOR_R0603_51R" R0603 1100,3375 r270 bottom
R102 "RESISTOR_R0603_51R" R0603 1100,4075 r90 bottom
R103 "R_R0603_10R" R0603 2550,460.68 r90 top
R104 "RESISTOR_R0603_100" R0603 2725,360.68 r0 top
R105 "RESISTOR_R0603_4.7K" R0603 2750,460.68 r270 top
R106 "R_R0805_1R" R0805#2 2652,900 r0 bottom
R107 "R_R0603_10R" R0603 3579.17,460.68 r90 top
R108 "RESISTOR_R0603_100" R0603 3754.17,360.68 r0 top
R109 "R_R0805_1R" R0805#2 3677,900 r0 bottom
R110 "RESISTOR_R0603_4.7K" R0603 3779.17,460.68 r270 top
R111 "R_R0603_10R" R0603 4600,460.68 r90 top
R112 "RESISTOR_R0603_100" R0603 4775,360.68 r0 top
R113 "R_R0805_1R" R0805#2 4702,900 r0 bottom
R114 "RESISTOR_R0603_4.7K" R0603 4800,460.68 r270 top
R115 "R_R0603_10R" R0603 5625,460.68 r90 top
R116 "RESISTOR_R0603_100" R0603 5800,360.68 r0 top
R117 "RESISTOR_R0603_4.7K" R0603 5825,460.68 r270 top
R118 "R_R0805_1R" R0805#2 5727,900 r0 bottom
R119 "R_R0603_10R" R0603 2600,6814.32 r270 top
R120 "RESISTOR_R0603_100" R0603 2425,6914.32 r180 top
R121 "R_R0805_1R" R0805#1 2500,6300 r0 bottom
R122 "RESISTOR_R0603_4.7K" R0603 2400,6814.32 r90 top
R123 "R_R0603_10R" R0603 3625,6814.32 r270 top
R124 "RESISTOR_R0603_100" R0603 3450,6914.32 r180 top
R125 "RESISTOR_R0603_4.7K" R0603 3425,6814.32 r90 top
R126 "R_R0805_1R" R0805#1 3525,6300 r0 bottom
R127 "R_R0603_10R" R0603 4525,6814.32 r270 top
R128 "RESISTOR_R0603_100" R0603 4350,6914.32 r180 top
R129 "R_R0805_1R" R0805#1 4425,6300 r0 bottom
R130 "RESISTOR_R0603_4.7K" R0603 4325,6814.32 r90 top
R131 "R_R0603_10R" R0603 5550,6814.32 r270 top
R132 "RESISTOR_R0603_100" R0603 5375,6914.32 r180 top
R133 "RESISTOR_R0603_4.7K" R0603 5350,6814.32 r90 top
R134 "R_R0805_1R" R0805#1 5450,6300 r0 bottom
T1 "LET0234_326UH_0_XFMR-PQ6562_T1_" XFMR-PQ6562_T1 7945,3615 r180 top
T2 "LET0234_326UH_0_XFMR-PQ6562_T2_" XFMR-PQ6562_T2 4740,3615 r180 top
U1 "MCR1101_0_SOICW-16_ACS733" SOICW-16 509.25,6190.75 r180 top
U2 "MC78L05F-TP_SOT-89-3L_MC78L05F-" SOT-89-3L 2070.75,6884.25 r90 top
U3 "MC78L05F-TP_TO252AB_LF50ABDT-TR" TO252AB 982.87,2595.22 r0 bottom
U4 "E1212S-2WR2_3_G1212S_2W11_R15P2" G1212S_2W11 2248.6,616.3 r90 top
U5 "E1212S-2WR2_3_G1212S_2W11_R15P2" G1212S_2W11 3273.6,616.3 r90 top
U6 "E1212S-2WR2_3_G1212S_2W11_R15P2" G1212S_2W11 5323.6,616.3 r90 top
U7 "E1212S-2WR2_3_G1212S_2W11_R15P2" G1212S_2W11 4298.6,616.3 r90 top
U8 "E1212S-2WR2_3_G1212S_2W11_R15P2" G1212S_2W11 2903.4,6658.7 r270 top
U9 "E1212S-2WR2_3_G1212S_2W11_R15P2" G1212S_2W11 3928.4,6658.7 r270 top
U10 "E1212S-2WR2_3_G1212S_2W11_R15P2" G1212S_2W11 4828.4,6658.7 r270 top
U11 "E1212S-2WR2_3_G1212S_2W11_R15P2" G1212S_2W11 5853.4,6658.7 r270 top
U12 "SI8661_3_WB_SOIC16_SI8662" WB_SOIC16 1125,3725 r0 bottom
U13 "UCC5350MC_SOIC8_DWV_UCC5350MC" SOIC8_DWV 2677,805.34 r90 top
U14 "UCC5350MC_SOIC8_DWV_UCC5350MC" SOIC8_DWV 3702,805.34 r90 top
U15 "UCC5350MC_SOIC8_DWV_UCC5350MC" SOIC8_DWV 4727,805.34 r90 top
U16 "UCC5350MC_SOIC8_DWV_UCC5350MC" SOIC8_DWV 5752,805.34 r90 top
U17 "UCC5350MC_SOIC8_DWV_UCC5350MC" SOIC8_DWV 2475,6469.66 r270 top
U18 "UCC5350MC_SOIC8_DWV_UCC5350MC" SOIC8_DWV 3500,6469.66 r270 top
U19 "UCC5350MC_SOIC8_DWV_UCC5350MC" SOIC8_DWV 4400,6469.66 r270 top
U20 "UCC5350MC_SOIC8_DWV_UCC5350MC" SOIC8_DWV 5425,6469.66 r270 top

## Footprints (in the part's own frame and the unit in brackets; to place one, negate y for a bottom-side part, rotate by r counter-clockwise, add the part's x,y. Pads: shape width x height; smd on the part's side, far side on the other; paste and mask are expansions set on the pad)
C0603#1 [mil] "C0603"
  rect 35x31 smd: 1(29.92,0) 2(-29.92,0)
  Multi-Layer keep-out region: 51.18,-19.69 51.18,19.69 -51.18,19.69 -51.18,-19.69 51.18,-19.69
  silkscreen extent -57,-26 57,26, body extent -32,-16 32,16, height 150
C0603#2 [mil] "C0603"
  rect 35x31 smd: 1(-29.92,0) 2(29.92,0)
  Multi-Layer keep-out region: -51.18,19.69 -51.18,-19.69 51.18,-19.69 51.18,19.69 -51.18,19.69
  silkscreen extent -57,-26 57,26, body extent -32,-16 32,16, height 150
C0805#1 [mil] "C0805"
  rect 43x50 smd: 1(-35.04,0) 2(35.04,0)
  TOP keep-out region: -60.24,28.35 -60.24,-28.35 59.84,-28.35 59.84,28.35 -60.24,28.35
  silkscreen extent -67,-35 67,35, body extent -39,-25 39,25, height 150
C0805#2 [mil] "C0805"
  rect 43x50 smd: 1(35.04,0) 2(-35.04,0)
  TOP keep-out region: 60.24,-28.35 60.24,28.35 -59.84,28.35 -59.84,-28.35 60.24,-28.35
  silkscreen extent -67,-35 67,35, body extent -39,-25 39,25, height 150
C1206#1 [mil] "C1206"
  rect 55x63 smd: 1(-55.12,0) 2(55.12,0)
  TOP keep-out region: -85.94,34.84 -85.94,-34.76 86.02,-34.76 86.02,34.84 -85.94,34.84
  silkscreen extent -95,-45 95,45, body extent -63,-32 63,32, height 150
C1206#2 [mil] "C1206"
  rect 55x63 smd: 1(55.12,0) 2(-55.12,0)
  TOP keep-out region: 85.94,-34.84 85.94,34.76 -86.02,34.76 -86.02,-34.84 85.94,-34.84
  silkscreen extent -95,-45 95,45, body extent -63,-32 63,32, height 150
C2220 [mm] "C2220"
  rect 1.905x5.08 smd: 1(-3,0) 2(3,0)
  TOP keep-out region: -4.04,2.59 -4.04,-2.59 4.04,-2.59 4.04,2.59 -4.04,2.59
  silkscreen extent -4.3,-2.85 4.3,2.85, body extent -2.8,-2.5 2.8,2.5, height 3.81
CAPFILM_31_5X12_5MM [mil] "CAPFILM_31_5X12_5MM"
  round 138 hole 39: 1(-541.34,0) 2(541.34,0)
  silkscreen extent -630,-256 630,256
CAPFILM_31_5X18_5MM [mil] "CAPFILM_31_5X18_5MM"
  rect 98x98 hole 47: 1(-541.34,0)
  round 98 hole 47: 2(541.34,0)
  silkscreen extent -620,-374 620,374, body extent -621,-375 621,375, height 150
CON_2MM54_5X1 [mil] "CON_2MM54_5X1"
  round 59 hole 40: 1(-193.11,6.89) 2(-93.11,6.89) 3(6.89,6.89) 4(106.89,6.89) 5(206.89,6.89)
  silkscreen extent -262,-62 262,62, body extent -267,-67 267,67, height 150
CON_2MM54_5X2 [mil] "CON_2MM54_5X2"
  round 59 hole 40: 1(-193.11,-43.11) 2(-193.11,56.89) 3(-93.11,-43.11) 4(-93.11,56.89) 5(6.89,-43.11) 6(6.89,56.89) 7(106.89,-43.11) 8(106.89,56.89) 9(206.89,-43.11) 10(206.89,56.89)
  silkscreen extent -262,-112 262,112, body extent -267,-117 267,117, height 150
CON_2MM54_6X2 [mil] "CON_2MM54_6X2"
  round 59 hole 39: 1(-250,-50) 2(-250,50) 3(-150,-50) 4(-150,50) 5(-50,-50) 6(-50,50) 7(50,-50) 8(50,50) 9(150,-50) 10(150,50) 11(250,-50) 12(250,50)
  silkscreen extent -310,-110 310,110, body extent -310,-110 310,110, height 150
CON_2MM54_12X2 [mil] "CON_2MM54_12X2"
  round 59 hole 39: 1(-550,-50) 2(-550,50) 3(-450,-50) 4(-450,50) 5(-350,-50) 6(-350,50) 7(-250,-50) 8(-250,50) 9(-150,-50) 10(-150,50) 11(-50,-50) 12(-50,50) 13(50,-50) 14(50,50) 15(150,-50) 16(150,50) 17(250,-50) 18(250,50) 19(350,-50) 20(350,50) 21(450,-50) 22(450,50) 23(550,-50) 24(550,50)
  silkscreen extent -610,-110 610,110, body extent -610,-110 610,110, height 150
CON_5MM_2X1 [mil] "CON_5MM_2X1"
  round 98 hole 47: 1(-99.22,17.71) 2(97.64,17.72)
  silkscreen extent -236,-148 198,148, body extent -199,-149 199,149, height 150
CRB [mil] "CRB"
  oval 380x180 / inner oval 307x130 / far side oval 380x180 hole 118 slot 295 at 0 deg: 1(-413.39,196.85) 2(413.39,196.85)
  silkscreen extent -591,-315 591,315, body extent -606,-316 606,316, height 150
ECAP_D8P3_5 [mil] "ECAP_D8P3_5"
  rect 50x50 hole 32: 1(-68.9,0)
  round 50 hole 32: 2(68.9,0)
  silkscreen extent -157,-169 169,169, body extent -158,-158 158,158, height 150
ECAP_D18P7_5 [mm] "ECAP_D18P7_5"
  round 3 hole 1.5: 1(0,-3.75) 2(0,3.75)
  silkscreen extent -9,-11.12 9,9, body extent -9.03,-9.03 9.03,9.03, height 3.81
G1212S_2W11 [mil] "G1212S_2W11"
  round 59 hole 40: 1(-300.55,113.53) 2(-200.55,113.53) 5(99.45,113.53) 6(199.45,113.53) 7(299.45,113.53)
  silkscreen extent -386,-194 383,192, body extent -385,-193 385,193, height 150
L6 [mil] "L6"
  oval 420x230 / inner oval 327x169 / far side oval 420x230 hole 157 slot 315 at 0 deg: 1(-669.29,-839.37) 3(669.29,-839.37)
  silkscreen extent -886,-800 886,972, body extent -900,-1000 900,1000, height 150
R0603 [mil] "R0603"
  rect 30x30 smd: 1(-29.92,0) 2(29.92,0)
  TOP keep-out region: -48.43,18.9 -48.43,-18.9 48.03,-18.9 48.03,18.9 -48.43,18.9
  silkscreen extent -55,-26 55,26, body extent -32,-16 32,16, height 150
R0805#1 [mil] "R0805"
  rect 39x47 smd: 1(-39.37,0) 2(39.37,0)
  TOP keep-out region: -62.2,26.77 -62.2,-26.77 62.2,-26.77 62.2,26.77 -62.2,26.77
  silkscreen extent -68,-32 68,32, body extent -39,-25 39,25, height 150
R0805#2 [mil] "R0805"
  rect 39x47 smd: 1(39.37,0) 2(-39.37,0)
  TOP keep-out region: 62.2,-26.77 62.2,26.77 -62.2,26.77 -62.2,-26.77 62.2,-26.77
  silkscreen extent -68,-32 68,32, body extent -39,-25 39,25, height 150
R1206#1 [mil] "R1206"
  rect 55x63 smd: 1(-55.12,0) 2(55.12,0)
  TOP keep-out region: -86.61,35.43 -86.61,-35.43 86.61,-35.43 86.61,35.43 -86.61,35.43
  silkscreen extent -93,-41 93,41, body extent -61,-32 61,32, height 150
R1206#2 [mil] "R1206"
  rect 55x63 smd: 1(55.12,0) 2(-55.12,0)
  TOP keep-out region: 86.61,-35.43 86.61,35.43 -86.61,35.43 -86.61,-35.43 86.61,-35.43
  silkscreen extent -93,-41 93,41, body extent -61,-32 61,32, height 150
SOD-123 [mil] "SOD-123"
  rect 40.16x55.12 smd: 1(-84.65,0) 2(84.65,0)
  silkscreen extent -133,-39 128,83, body extent -120,-34 120,34, height 150
SOIC8_DWV [mil] "SOIC8_DWV"
  rect 70x25 smd: 1(-208.66,75) 2(-208.66,25) 3(-208.66,-25) 4(-208.66,-75) 5(208.66,-75) 6(208.66,-25) 7(208.66,25) 8(208.66,75)
  silkscreen extent -284,-117 150,117, body extent -247,-118 247,118, height 150
SOICW-16 [mil] "SOICW-16"
  oval 90x25 smd: 1(-180.24,175) 2(-180.24,125) 3(-180.24,75) 4(-180.24,25) 5(-180.24,-25) 6(-180.24,-75) 7(-180.24,-125) 8(-180.24,-175) 9(180.24,-175) 10(180.24,-125) 11(180.24,-75) 12(180.24,-25) 13(180.24,25) 14(180.24,75) 15(180.24,125) 16(180.24,175)
  silkscreen extent -265,-203 281,203, body extent -203,-203 203,203, height 150
SOT-23 [mil] "SOT-23"
  oval 24x50 smd: 1(-37.4,-39.76) 2(37.4,-39.76) 3(0,39.76)
  silkscreen extent -70,-100 59,75, body extent -60,-52 60,52, height 150
SOT-89-3L [mil] "SOT-89-3L"
  rect 63x24 smd: 1(-74.78,53.08) 3(-74.78,-65.03)
  rect 79x28 smd: 2(-66.9,-5.99)
  rect 134x79 smd: ""(39.4,-5.99)
  silkscreen extent -87,-97 51,96, body extent -109,-98 109,98, height 150
TH47_CR98 [mil] "TH47_CR98"
  round 98 hole 47: 1(0,0)
  silkscreen extent -66,-66 66,66, body extent -66,-66 66,66, height 150
THREAD4_9P9X5_1110X920 [mil] "THREAD4_9P9X5_1110X920"
  round 130 / inner round 99 / far side round 130 hole 87: 1(194.88,98.42) 2(-194.88,98.42) 3(-194.88,-98.42) 4(194.88,-98.42)
  silkscreen extent -219,-181 219,181, body extent -263,-182 263,182, height 150
TO252AB [mil] "TO252AB"
  rect 63x118 smd: 1(-90.55,167.41) 3(90.55,167.41)
  rect 264x264 smd: 2(0,-94.4)
  silkscreen extent -146,-239 150,264, body extent -135,-229 135,229, height 150
TO-247-4L#1 [mil] "TO-247-4L"
  rect 78x141 hole 67: 1(-200,482.28)
  oval 78x141 hole 67: 2(0,482.28) 3(100,482.28) 4(200,482.28)
  silkscreen extent -319,-620 319,620, body extent -319,-621 319,621, height 150
TO-247-4L#2 [mil] "TO-247-4L"
  rect 78x141 hole 67: 1(200,-482.28)
  oval 78x141 hole 67: 2(0,-482.28) 3(-100,-482.28) 4(-200,-482.28)
  silkscreen extent -319,-620 319,620, body extent -319,-621 319,621, height 150
WB_SOIC16 [mil] "WB_SOIC16"
  rect 25x65 smd: 1(175,192) 2(125,192) 3(75,192) 4(25,192) 5(-25,192) 6(-75,192) 7(-125,192) 8(-175,192) 9(-175,-192) 10(-125,-192) 11(-75,-192) 12(-25,-192) 13(25,-192) 14(75,-192) 15(125,-192) 16(175,-192)
  silkscreen extent -212,-128 212,260, body extent -215,-230 215,230, height 150
XFMR-PQ6562_T1 [mil] "XFMR-PQ6562_T1"
  oval 420x230 / inner oval 327x169 / far side oval 420x230 hole 157 slot 315 at 0 deg: 1(787.4,1062.99) 4(-787.4,1062.99) 7(492.13,-1062.99) 8(2106.3,-1062.99)
  silkscreen extent -1339,-1220 1339,1220, body extent -1339,-1220 1339,1220, height 150
XFMR-PQ6562_T2 [mil] "XFMR-PQ6562_T2"
  oval 420x230 / inner oval 327x169 / far side oval 420x230 hole 157 slot 315 at 0 deg: 1(787.4,1062.99) 4(-787.4,1062.99) 7(-2106.3,-1062.99) 8(-492.13,-1062.99)
  silkscreen extent -1339,-1220 1339,1220, body extent -1339,-1220 1339,1220, height 150

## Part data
C1 C2 C4 C5 C7 C8 C10 C14 C15 C22 C23 C27 C28 C32 C33 C34 C35 C36 C37 C42 C43 C44 C45 C46 C47 C48 C49 C50 C51 C52 C53 C185 C186 C633: library part "CAP NP_Dup1"
C20 C21 C56 C57 C58 C59 C60 C61 C62 C64 C65 C66 C67 C68 C69 C70 C71 C72 C73 C74 C75 C76 C77 C78 C79 C80 C81 C82 C83 C84 C85 C86 C87 C88 C89 C90 C91 C92 C93 C94 C95 C96 C97 C98 C99 C100 C101 C102 C103 C104 C105 C106 C107 C108 C109 C110 C111 C112 C113 C114 C115 C116 C117 C118 C119 C120 C121 C122 C123 C124 C125 C126 C127 C128 C129 C130 C131 C132 C134 C135 C136 C137 C138 C139 C141 C142 C143 C144 C145 C146 C148 C149 C150 C151 C152 C153 C155 C156 C157 C158 C159 C160 C161 C162 C163 C164 C165 C166 C167 C168 C169 C170 C171 C172 C173 C174 C175 C176 C177 C178 C179 C180 C181 C182 C183 C184: library part "CAP NP"
C25 C26 C39 C40 C54 C55: library part "CAP POL"
CON1 CON2 CON3 CON4: library part Connecter
CR1 CR2 CR3 CR4 CR5: library part 3PIN
CT1 CT2 CT5 CT6 CT7 CT8: library part CON1_2
D1 D2 D7 D8: library part DIODE_0
D3 D4 D5 D6 D9 D10 D11 D12: library part FMMD6100/SOT_0
J1: library part CON24A
J2 J3: library part CON12A
J4: library part CON2
J5: library part CON10A
J6: library part CON5
L1: library part 126LNS_1
L2: library part 126LNS_5
Q1 Q2 Q3 Q4 Q7 Q16 Q17 Q18: library part C3M0065090J_4
R1 R2 R4 R5 R8 R9 R14 R15 R19 R20 R21 R22 R36 R37 R38 R39 R40 R43 R44 R45 R48 R49 R52 R53 R56 R57 R58 R59 R62 R64 R65 R66 R72 R73 R75 R76 R103 R106 R107 R109 R111 R113 R115 R118 R119 R121 R123 R126 R127 R129 R131 R134: library part R
R34 R41 R42 R46 R47 R50 R51 R54 R55 R60 R61 R69 R70 R84 R85 R86 R87 R88 R89 R90 R91 R92 R93 R94 R95 R96 R97 R98 R99 R100 R101 R102 R104 R105 R108 R110 R112 R114 R116 R117 R120 R122 R124 R125 R128 R130 R132 R133: library part RESISTOR
R63 R67 R68 R71 R74 R77 R78 R79: library part RESISTOR_Dup1
T1 T2: library part LET0234_326uH_0
U1: library part MCR1101_0
U2 U3: library part MC78L05F-TP
U4 U5 U6 U7 U8 U9 U10 U11: library part E1212S-2WR2_3
U12: library part Si8661_3
U13 U14 U15 U16 U17 U18 U19 U20: library part UCC5350MC

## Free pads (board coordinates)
  round 180 hole 122: 1(150,150) 1(150,6936.6) 1(2010,3645) 1(6195,210) 1(6340,4370) 1(7645,6920) 1(8285,2170)
  round 40 / inner round 60 / far side round 40 all layers, no hole: 1(250,6675) 1(455,275) 1(7125,900)

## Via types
v1: diameter 24, hole 12, TOP to BOTTOM, tented both sides, 199 vias

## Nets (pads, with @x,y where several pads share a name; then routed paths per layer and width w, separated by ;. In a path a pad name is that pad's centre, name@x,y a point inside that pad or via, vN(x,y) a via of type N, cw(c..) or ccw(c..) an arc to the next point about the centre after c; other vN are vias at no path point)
-3V_PSW5: C85.2 C86.2 C137.2 C139.2 U4.5 U13.8 | length 653.7
  TOP w30: U4.5@2135.07,715.75 2247.67,715.75 C139.2@2527,995.08 v1(2562,995.08) 2583.08,995.08 U13.8@2602,1014
  BOTTOM w30: v1(2562,995.08) 2596.88,995.08 C137.2@2616.96,975
-3V_PSW6: C89.2 C91.2 C145.2 C146.2 U5.5 U14.8 | length 653.7
  TOP w30: U5.5@3160.07,715.75 3272.67,715.75 C146.2@3552,995.08 v1(3587,995.08) 3608.08,995.08 U14.8@3627,1014
  BOTTOM w30: v1(3587,995.08) 3621.88,995.08 C145.2@3641.96,975
-3V_PSW7: C87.2 C88.2 C151.2 C153.2 U7.5 U15.8 | length 653.7
  TOP w30: U7.5@4185.07,715.75 4297.67,715.75 C153.2@4577,995.08 v1(4612,995.08) 4633.08,995.08 U15.8@4652,1014
  BOTTOM w30: v1(4612,995.08) 4646.88,995.08 C151.2@4666.96,975
-3V_PSW8: C90.2 C92.2 C159.2 C160.2 U6.5 U16.8 | length 653.7
  TOP w30: U6.5@5210.07,715.75 5322.67,715.75 C160.2@5602,995.08 v1(5637,995.08) 5658.08,995.08 U16.8@5677,1014
  BOTTOM w30: v1(5637,995.08) 5671.88,995.08 C159.2@5691.96,975
-3V_PSW9: C113.2 C114.2 C164.2 C166.2 U8.5 U17.8 | length 688.7
  TOP w30: U17.8@2550,6261 2550,6334.58 v1(2590,6374.58) C166.2@2625,6374.58 2832.26,6374.58 U8.5@3016.93,6559.25
  BOTTOM w30: C164.2@2535.04,6375 2589.58,6375 v1(2590,6374.58)
-3V_PSW10: C123.2 C124.2 C171.2 C172.2 U9.5 U18.8 | length 688.7
  TOP w30: U18.8@3575,6261 3575,6334.58 v1(3615,6374.58) C172.2@3650,6374.58 3857.26,6374.58 U9.5@4041.93,6559.25
  BOTTOM w30: C171.2@3560.04,6375 3614.58,6375 v1(3615,6374.58)
-3V_PSW11: C125.2 C126.2 C176.2 C178.2 U10.5 U19.8 | length 688.7
  TOP w30: U19.8@4475,6261 4475,6334.58 v1(4515,6374.58) C178.2@4550,6374.58 4757.26,6374.58 U10.5@4941.93,6559.25
  BOTTOM w30: C176.2@4460.04,6375 4514.58,6375 v1(4515,6374.58)
-3V_PSW12: C127.2 C128.2 C183.2 C184.2 U11.5 U20.8 | length 688.7
  TOP w30: U20.8@5500,6261 5500,6334.53 v1(5540,6374.53) 5540.05,6374.58 C184.2@5575,6374.58 5782.26,6374.58 U11.5@5966.93,6559.25
  BOTTOM w30: C183.2@5485.04,6375 5539.53,6375 v1(5540,6374.53)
